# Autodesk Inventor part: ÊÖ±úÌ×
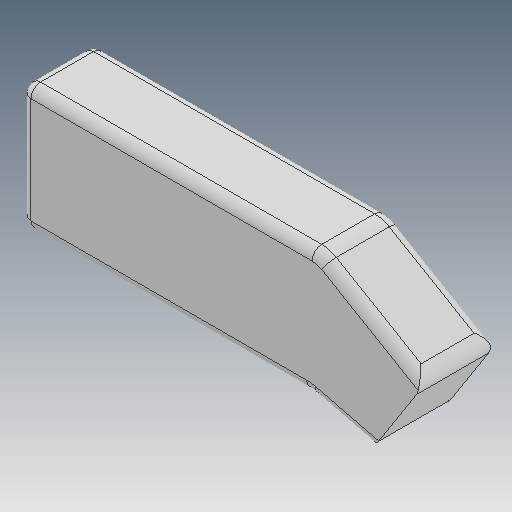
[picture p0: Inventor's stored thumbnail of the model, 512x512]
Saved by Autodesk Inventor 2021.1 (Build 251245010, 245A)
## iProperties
Created: 2020-03
Part Number: ÊÖ±úÌ×
Material: Ogólny
Document SubType Name: Modeling
Designer: user
Density: 1 g/cm^3
Appearance: Domyślna
Author: user
Revision Number: ÈÎºÎ
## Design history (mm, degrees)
feature "µ¹½Ç1"
node "Bryła1"
